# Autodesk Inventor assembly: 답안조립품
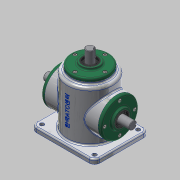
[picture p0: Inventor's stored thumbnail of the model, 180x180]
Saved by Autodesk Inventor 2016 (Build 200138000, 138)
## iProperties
Created: 2021-02
Part Number: 답안조립품
Material: 일반
Document SubType Name: Assembly
Designer: user
Author: user
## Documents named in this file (16)
- C:\Users\user\Desktop\710206V1001\답안조립품.iam
- C:\Users\user\Desktop\710206V1001\본체.ipt
- C:\Users\user\Desktop\710206V1001\메인 베벨기어.ipt
- C:\Users\user\Desktop\710206V1001\메인 축.ipt
- 메인 축.ipt
- C:\Users\user\Desktop\710206V1001\베어링 6203.ipt
- C:\Users\user\Desktop\710206V1001\볼트 M4.ipt
- 볼트 M4.ipt
- C:\Users\user\Desktop\710206V1001\서브 베벨기어.ipt
- C:\Users\user\Desktop\710206V1001\서브 축.ipt
- 서브 축.ipt
- C:\Users\user\Desktop\710206V1001\오일 실.ipt
- 오일 실.ipt
- C:\Users\user\Desktop\710206V1001\커버.ipt
- C:\Users\user\Desktop\710206V1001\키 4x4.ipt
- C:\Users\user\Desktop\710206V1001\키 5x5.ipt
